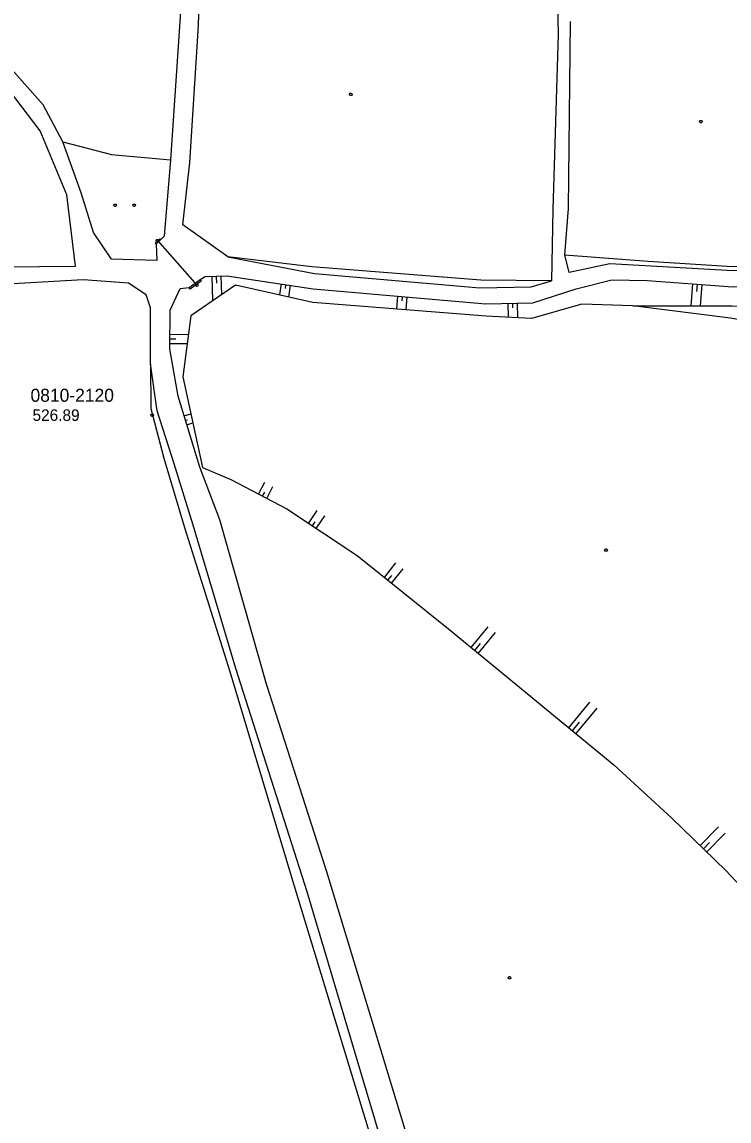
# Model space of a CAD drawing. Extents: x -664960 to -662754, y -993849 to -991145.
# Drawn here: x -664152.5 to -663968.2, y -992520.3 to -992233.7 of the extents above; entities that cross this region are included whole.
import ezdxf

# ---------------------------------------------------------------- set-up
doc = ezdxf.new("R2010")
doc.units = 0
for name, color, linetype in [('Vrstva 1', 7, 'Continuous'), ('Vrstva 13', 7, 'Continuous'), ('Vrstva 23', 7, 'Continuous'), ('Vrstva 24', 7, 'Continuous'), ('Vrstva 27', 7, 'Continuous'), ('Vrstva 63', 7, 'Continuous'), ('Vrstva 8', 7, 'Continuous')]:
    doc.layers.add(name, color=color, linetype=linetype)

msp = doc.modelspace()

# ---------------------------------------------------------------- linework, layer by layer
at = {"layer": 'Vrstva 13'}
for points in [[(-664066.622, -992252.26), (-664066.442, -992252.56), (-664066.622, -992252.86), (-664066.982, -992252.86), (-664067.162, -992252.56), (-664066.982, -992252.26), (-664066.622, -992252.26)], [(-663975.339, -992259.363), (-663975.159, -992259.663), (-663975.339, -992259.963), (-663975.699, -992259.963), (-663975.879, -992259.663), (-663975.699, -992259.363), (-663975.339, -992259.363)], [(-664128, -992281.164), (-664127.82, -992281.464), (-664128, -992281.764), (-664128.36, -992281.764), (-664128.54, -992281.464), (-664128.36, -992281.164), (-664128, -992281.164)], [(-664123.052, -992281.164), (-664122.872, -992281.464), (-664123.052, -992281.764), (-664123.412, -992281.764), (-664123.592, -992281.464), (-664123.412, -992281.164), (-664123.052, -992281.164)], [(-664000.084, -992371.135), (-663999.904, -992371.435), (-664000.084, -992371.735), (-664000.444, -992371.735), (-664000.624, -992371.435), (-664000.444, -992371.135), (-664000.084, -992371.135)], [(-664025.203, -992482.657), (-664025.023, -992482.957), (-664025.203, -992483.257), (-664025.563, -992483.257), (-664025.743, -992482.957), (-664025.563, -992482.657), (-664025.203, -992482.657)]]:
    msp.add_lwpolyline(points, dxfattribs=at)
at = {"layer": 'Vrstva 23'}
for points in [[(-664098.79, -992294.95), (-664076.24, -992299.28), (-664033.13, -992303.03), (-664019.76, -992302.77), (-664014.48, -992301.2)], [(-663928.724, -992293.289), (-663939.93, -992296.31), (-663952.53, -992298.11), (-663967.1, -992298.57), (-663999.28, -992296.79), (-664009.84, -992299.04)], [(-664099.12, -992299.85), (-664076.61, -992303.27), (-664031.58, -992307.16), (-664019.3, -992306.93), (-664008.02, -992303.25), (-663998.74, -992300.94), (-663989.52, -992301.13), (-663967.2, -992302.74), (-663938.94, -992301.03), (-663927.353, -992297.442)], [(-663997.38, -992776.83), (-664005.01, -992738.66), (-664013.53, -992700.45), (-664027.03, -992643.59), (-664049.65, -992557.23), (-664058.31, -992527.13), (-664078.14, -992460.53), (-664096.77, -992402.28), (-664107.89, -992364.93), (-664112.84, -992348.94), (-664117.28, -992335.14), (-664119, -992322.82), (-664119, -992308.2)], [(-663990.89, -992778.63), (-663998.43, -992738.22), (-664009.08, -992695.49), (-664019.8, -992648.86), (-664043.31, -992556.7), (-664052, -992524.61), (-664073.04, -992455.33), (-664088.77, -992406.41), (-664100.89, -992363.53), (-664106.12, -992349.76), (-664111.81, -992331.24), (-664113.9, -992318.89), (-664113.87, -992308.88)]]:
    msp.add_lwpolyline(points, dxfattribs=at)
at = {"layer": 'Vrstva 24'}
msp.add_line((-664117.18, -992290.71), (-664106.92, -992302.32), dxfattribs=at)
for points in [[(-664117.75, -992291.34), (-664116.55, -992290.25), (-664116.38, -992290.52), (-664117.5, -992291.62), (-664117.75, -992291.34)], [(-664116.836, -992290.646), (-664116.942, -992290.98), (-664117.286, -992291.044), (-664117.524, -992290.774), (-664117.418, -992290.44), (-664117.074, -992290.376), (-664116.836, -992290.646)], [(-664108.88, -992302.95), (-664106.03, -992300.83), (-664105.71, -992301.18), (-664108.65, -992303.38), (-664108.88, -992302.95)], [(-664106.576, -992302.256), (-664106.682, -992302.59), (-664107.026, -992302.654), (-664107.264, -992302.384), (-664107.158, -992302.05), (-664106.814, -992301.986), (-664106.576, -992302.256)]]:
    msp.add_lwpolyline(points, dxfattribs=at)
at = {"layer": 'Vrstva 27'}
for points in [[(-664136.56, -991981.24), (-664136.89, -991987.76), (-664134.9, -992004.59), (-664128.78, -992051.29), (-664125.55, -992095.45), (-664123.48, -992115.18), (-664118.48, -992141.38), (-664113.62, -992159.36), (-664110.38, -992176.55), (-664109.39, -992189.71), (-664111.04, -992229.69), (-664113.75, -992269.61), (-664115.45, -992289.53), (-664116.38, -992290.52)], [(-664098.79, -992294.95), (-664110.54, -992286.58), (-664108.77, -992270.34), (-664106.52, -992236.03), (-664104.5, -992190.33), (-664105.14, -992175.85), (-664107.23, -992164.98), (-664114.59, -992137.29), (-664118.86, -992115.21), (-664121.07, -992094.42), (-664124.26, -992054.77), (-664131.31, -991997.85), (-664131.26, -991990.95)], [(-664117.5, -992291.62), (-664117.31, -992295.87), (-664129.11, -992295.54), (-664133.87, -992288.61), (-664137.02, -992278.21), (-664141.86, -992264.91), (-664146.92, -992255.28), (-664155.82, -992245.31), (-664165.78, -992239.53), (-664185.71, -992234.12), (-664212.61, -992229.72), (-664221.65, -992228.24), (-664223.59, -992224.12), (-664217.7, -992212.51), (-664218.34, -992203.48), (-664220.98, -992191.76), (-664223.6, -992172.7), (-664224.71, -992127.96), (-664223.31, -992115.6), (-664227.78, -992112.81), (-664243.09, -992113.03)], [(-663999.651, -992198.94), (-664009.165, -992214.188), (-664013.006, -992225.502), (-664012.717, -992236.9)], [(-664138.52, -992297.4), (-664140.75, -992278.72), (-664147.75, -992262.05), (-664155.69, -992251.52), (-664170.33, -992243.26), (-664187.34, -992238.46), (-664213.22, -992234.29)], [(-664009.84, -992299.04), (-664011.01, -992294.41), (-664010.03, -992282.31), (-664009.545, -992233.58)], [(-664012.717, -992236.9), (-664014.11, -992282.59), (-664014.48, -992301.2)], [(-664119, -992308.2), (-664120.11, -992304.84), (-664124.67, -992301.76), (-664136.54, -992300.89), (-664156.33, -992302.08), (-664177.07, -992301.85), (-664194.27, -992300.97), (-664207.93, -992299.41), (-664216.54, -992298.34), (-664217.9, -992291.83), (-664178.56, -992297.06), (-664157.27, -992297.5), (-664138.52, -992297.4)], [(-664106.03, -992300.83), (-664104.7, -992300.06), (-664099.12, -992299.85)], [(-664113.87, -992308.88), (-664111.29, -992303.2), (-664108.88, -992302.95)]]:
    msp.add_lwpolyline(points, dxfattribs=at)
at = {"layer": 'Vrstva 63'}
for p, q in [((-664103.026, -992299.997), (-664102.785, -992306.406)), ((-664101.827, -992299.952), (-664101.756, -992301.833)), ((-664100.628, -992299.907), (-664100.444, -992304.793)), ((-664084.959, -992302.001), (-664085.398, -992304.887)), ((-664083.773, -992302.182), (-664083.923, -992303.172)), ((-664082.586, -992302.362), (-664083.051, -992305.421)), ((-663977.698, -992301.983), (-663978.113, -992307.736)), ((-663976.501, -992302.069), (-663976.637, -992303.956)), ((-663975.304, -992302.155), (-663975.707, -992307.737)), ((-664054.568, -992305.174), (-664054.863, -992308.583)), ((-664053.373, -992305.277), (-664053.47, -992306.409)), ((-664052.177, -992305.381), (-664052.47, -992308.77)), ((-664025.834, -992307.052), (-664025.766, -992310.715)), ((-664024.635, -992307.03), (-664024.611, -992308.278)), ((-664023.435, -992307.007), (-664023.363, -992310.843)), ((-664113.889, -992315.135), (-664109.139, -992315.15)), ((-664113.896, -992317.535), (-664109.453, -992317.549)), ((-664113.892, -992316.335), (-664112.362, -992316.34)), ((-664110.212, -992336.441), (-664108.475, -992335.907)), ((-664109.86, -992337.588), (-664109.313, -992337.42)), ((-664109.507, -992338.735), (-664107.961, -992338.26)), ((-664090.82, -992356.829), (-664089.185, -992353.721)), ((-664088.696, -992357.946), (-664087.061, -992354.839)), ((-664089.758, -992357.388), (-664089.213, -992356.353)), ((-664077.781, -992364.467), (-664075.575, -992361.139)), ((-664076.781, -992365.13), (-664076.046, -992364.022)), ((-664075.781, -992365.793), (-664073.575, -992362.465)), ((-664058.034, -992378.558), (-664055.003, -992374.788)), ((-664057.098, -992379.31), (-664056.089, -992378.055)), ((-664056.163, -992380.062), (-664053.132, -992376.292)), ((-664035.405, -992396.843), (-664030.949, -992391.405)), ((-664033.548, -992398.364), (-664029.092, -992392.926)), ((-664034.477, -992397.604), (-664032.993, -992395.793)), ((-664009.941, -992417.793), (-664004.441, -992411.13)), ((-664008.09, -992419.32), (-664002.59, -992412.658)), ((-664009.015, -992418.557), (-664007.184, -992416.338)), ((-663975.701, -992448.487), (-663970.931, -992443.564)), ((-663974.839, -992449.322), (-663973.251, -992447.683)), ((-663973.977, -992450.157), (-663969.207, -992445.234))]:
    msp.add_line(p, q, dxfattribs=at)
for points in [[(-664141.86, -992264.91), (-664129.12, -992268.23), (-664113.75, -992269.61)], [(-664011.01, -992294.41), (-663989.25, -992296.04), (-663967.33, -992297.46), (-663939.93, -992296.31), (-663928.776, -992291.612), (-663916.25, -992286.35), (-663919.185, -992268.764)], [(-664014.48, -992301.2), (-664032.92, -992301.04), (-664076.91, -992297.51), (-664098.79, -992294.95)], [(-663993.24, -992307.73), (-664006.57, -992307.24), (-664019.66, -992311.04), (-664031.5, -992310.41), (-664076.64, -992306.88), (-664096.81, -992302.29), (-664108.51, -992310.35), (-664110.59, -992326.23), (-664105.43, -992349.84)], [(-663993.24, -992307.73), (-663967.39, -992307.74), (-663944.97, -992308.53), (-663921.06, -992310.14), (-663920.8, -992327.38)], [(-663921.787, -992353.692), (-663922.75, -992352.03), (-663925.27, -992332.48), (-663928.42, -992321.87), (-663934.46, -992317.11), (-663967.79, -992310.91), (-663993.24, -992307.73)], [(-664119, -992322.82), (-664118.91, -992334.49), (-664115.54, -992347.49), (-664110.14, -992365.57), (-664098.26, -992403.07), (-664082.2, -992456.72), (-664059.59, -992531.27), (-664053.27, -992554.58), (-664029.83, -992642.01), (-664015.6, -992700.81), (-664007.21, -992738.41), (-663999.43, -992777.06)], [(-664105.43, -992349.84), (-664098.06, -992353.02), (-664083.48, -992360.69), (-664065.12, -992372.86), (-664041.34, -992391.98), (-664023.79, -992406.36), (-663998.23, -992427.46), (-663983.12, -992441.3), (-663969.02, -992454.96), (-663960.12, -992464.52), (-663946.01, -992481.7), (-663938.74, -992491.15), (-663935.14, -992506.14), (-663931.481, -992518.089)]]:
    msp.add_lwpolyline(points, dxfattribs=at)
at = {"layer": 'Vrstva 8'}
msp.add_lwpolyline([(-664118.39, -992335.95), (-664118.21, -992336.25), (-664118.39, -992336.55), (-664118.75, -992336.55), (-664118.93, -992336.25), (-664118.75, -992335.95), (-664118.39, -992335.95)], dxfattribs=at)

# ---------------------------------------------------------------- texts
at = {"layer": 'Vrstva 1'}
msp.add_text('0810-2120', height=3.4, dxfattribs=at).set_placement((-664150.25, -992332.74))
at = {"layer": 'Vrstva 63'}
msp.add_text('526.89', height=3, dxfattribs=at).set_placement((-664149.726, -992337.72))

doc.saveas('drawing.dxf')
